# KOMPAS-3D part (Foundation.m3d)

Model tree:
1. Plane XY
2. Plane ZX
3. Plane ZY
4. X Axis
5. Y Axis
6. Z Axis
7. Origin
8. Sketch:1
9. Extrude:1
     Wall Thickness 1 = 1; Wall Thickness 2 = 1; Distance 1 = 1200; Distance 2 = 10

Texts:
  Steel DIN 17102
  Three Point Plane
  Plane at Angle
  Line and Point Plane
  Axis through Two Vertices
  Axis of Feature
  Axis of Conical Surface
  Axis through Edge
  Trim by Surface
  Trim by Sketch
  Feature with No History
  Intersection Axis of Two Planes
  Two Line Plane
  Line and Face Plane
  Bend by line
  Hole in sheet body
  Cut in sheet body
  Point in CM
  Linear Dimension from Line to Point
  Surface Finish Symbol
  Geometric Tolerance Symbol
  Leader #1
  Leader #2
  Leader #3
  Shape Deviations and Datum
  Node point number
  Mark of coordination axis
  Node point designation
  Mark/Reference designation with leader
  Mark/reference designation on line
  Mark/Reference designation without leader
